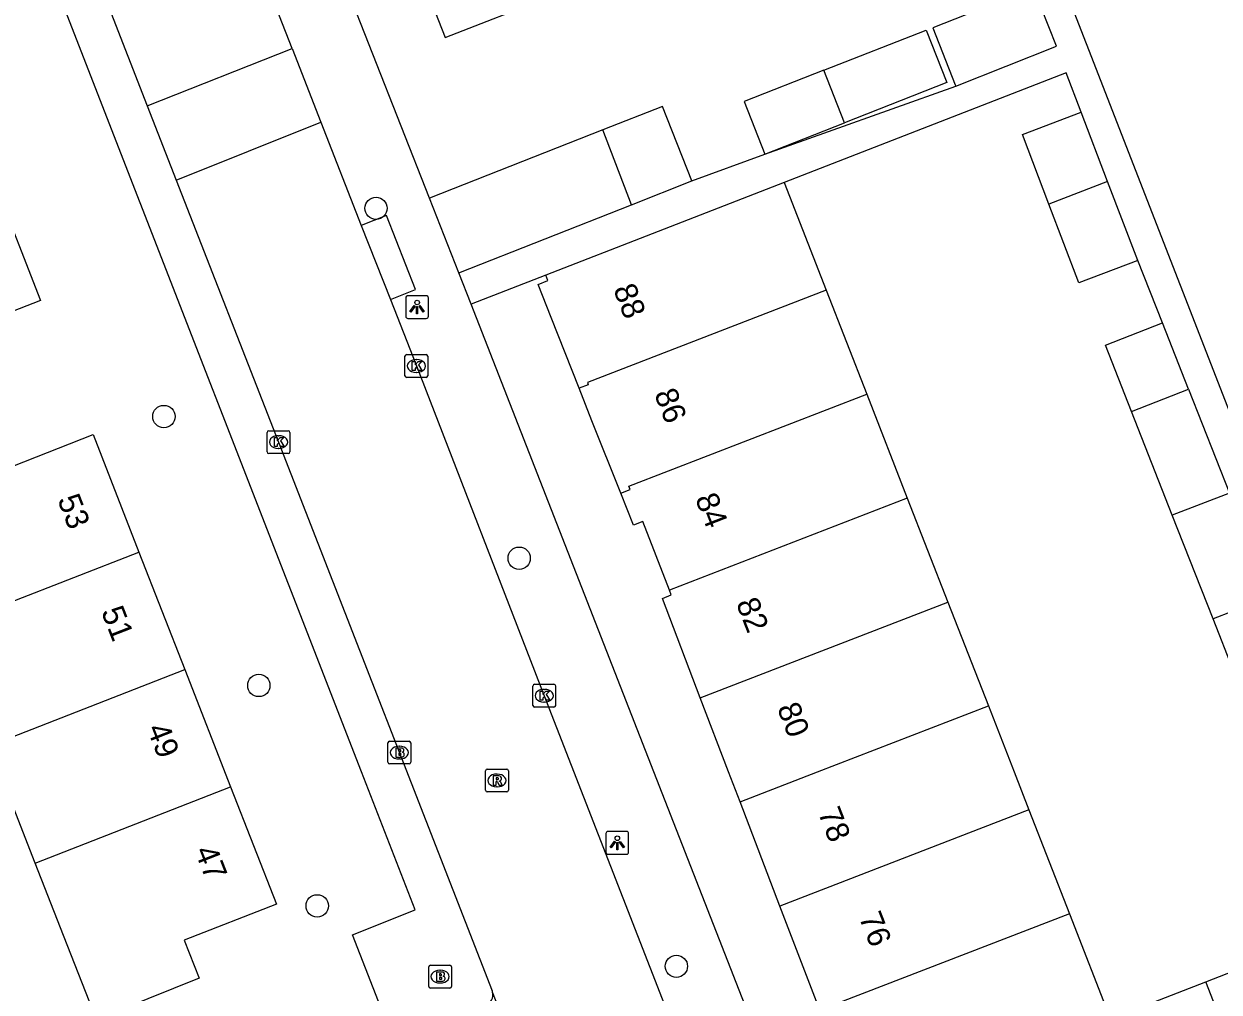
# Model space of a CAD drawing. Extents: x 159689 to 160786, y 387323 to 388339.
# Drawn here: x 159916.1 to 159968.5, y 387740.3 to 387782.8 of the extents above; entities that cross this region are included whole.
import ezdxf

# ---------------------------------------------------------------- set-up
doc = ezdxf.new("R2010")
doc.units = 0
for name, color, linetype in [('IMGEO_Boom', 7, 'Continuous'), ('IMGEO_Brandkraan', 7, 'Continuous'), ('IMGEO_Kolk', 7, 'Continuous'), ('IMGEO_Lichtpunt', 7, 'Continuous'), ('IMGEO_Pand', 7, 'Continuous'), ('IMGEO_Pand_nummerreeks', 7, 'Continuous'), ('IMGEO_Rijbaan_lokaal_open', 7, 'Continuous'), ('IMGEO_Rioolput', 7, 'Continuous'), ('IMGEO_Voetpad_open', 7, 'Continuous')]:
    doc.layers.add(name, color=color, linetype=linetype)

msp = doc.modelspace()

# ---------------------------------------------------------------- linework, layer by layer
at = {"layer": 'IMGEO_Boom'}
for centre in [(159931.561, 387774.715), (159922.264, 387765.584), (159937.836, 387759.371), (159926.425, 387753.791), (159928.983, 387744.127), (159944.727, 387741.478)]:
    msp.add_circle(centre, 0.489, dxfattribs=at)
at = {"layer": 'IMGEO_Brandkraan'}
for p, q in [((159932.082, 387750.423), (159932.082, 387751.275)), ((159932.157, 387751.349), (159933.009, 387751.349)), ((159932.57, 387751.129), (159932.595, 387751.129)), ((159933.083, 387751.275), (159933.083, 387750.423)), ((159932.593, 387750.569), (159932.568, 387750.569)), ((159933.009, 387750.349), (159932.157, 387750.349)), ((159933.945, 387741.525), (159934.797, 387741.525)), ((159933.87, 387740.599), (159933.87, 387741.451)), ((159934.358, 387741.305), (159934.383, 387741.305)), ((159934.871, 387741.451), (159934.871, 387740.599)), ((159934.797, 387740.525), (159933.945, 387740.525)), ((159934.381, 387740.745), (159934.356, 387740.745))]:
    msp.add_line(p, q, dxfattribs=at)
for points in [[(159932.082, 387750.423), (159932.082, 387751.275)], [(159932.157, 387751.349), (159933.009, 387751.349)], [(159932.43, 387751.049), (159932.43, 387750.649), (159932.643, 387750.649)], [(159932.661, 387751.049), (159932.43, 387751.049)], [(159932.609, 387750.968), (159932.555, 387750.968), (159932.555, 387750.892)], [(159933.083, 387751.275), (159933.083, 387750.423)], [(159932.555, 387750.892), (159932.608, 387750.892)], [(159932.617, 387750.816), (159932.555, 387750.816), (159932.555, 387750.735)], [(159932.555, 387750.735), (159932.617, 387750.735)], [(159933.009, 387750.349), (159932.157, 387750.349)], [(159933.945, 387741.525), (159934.797, 387741.525)], [(159933.87, 387740.599), (159933.87, 387741.451)], [(159934.218, 387741.225), (159934.218, 387740.825), (159934.431, 387740.825)], [(159934.449, 387741.225), (159934.218, 387741.225)], [(159934.397, 387741.144), (159934.343, 387741.144), (159934.343, 387741.068)], [(159934.343, 387741.068), (159934.396, 387741.068)], [(159934.405, 387740.992), (159934.343, 387740.992), (159934.343, 387740.911)], [(159934.871, 387741.451), (159934.871, 387740.599)], [(159934.797, 387740.525), (159933.945, 387740.525)], [(159934.343, 387740.911), (159934.405, 387740.911)]]:
    msp.add_lwpolyline(points, dxfattribs=at)
for centre, radius, start, end in [((159932.159, 387751.273), 0.0765, 91.552, 178.448), ((159932.159, 387751.273), 0.0765, 91.552, 178.448), ((159932.61, 387750.93), 0.0379, 267.8285, 90.9355), ((159932.665, 387750.904), 0.145, 59.4692, 91.5367), ((159932.69, 387750.951), 0.0922, 285.5137, 58.1501), ((159933.007, 387751.273), 0.0765, 1.552, 88.448), ((159933.007, 387751.273), 0.0765, 1.552, 88.448), ((159932.159, 387750.425), 0.0765, 181.552, 268.448), ((159932.159, 387750.425), 0.0765, 181.552, 268.448), ((159932.618, 387750.775), 0.0404, 269.8759, 90.5077), ((159932.649, 387750.9), 0.251, 268.6676, 293.5347), ((159932.695, 387750.759), 0.105, 301.3115, 78.989), ((159933.007, 387750.425), 0.0765, 271.552, 358.448), ((159933.007, 387750.425), 0.0765, 271.552, 358.448), ((159933.947, 387741.449), 0.0765, 91.552, 178.448), ((159933.947, 387741.449), 0.0765, 91.552, 178.448), ((159934.795, 387741.449), 0.0765, 1.552, 88.448), ((159934.795, 387741.449), 0.0765, 1.552, 88.448), ((159934.398, 387741.106), 0.0379, 267.8285, 90.9355), ((159934.406, 387740.951), 0.0404, 269.8759, 90.5077), ((159934.453, 387741.08), 0.145, 59.4692, 91.5367), ((159934.478, 387741.127), 0.0922, 285.5137, 58.1501), ((159934.483, 387740.935), 0.105, 301.3115, 78.989), ((159933.947, 387740.601), 0.0765, 181.552, 268.448), ((159933.947, 387740.601), 0.0765, 181.552, 268.448), ((159934.437, 387741.076), 0.251, 268.6676, 293.5347), ((159934.795, 387740.601), 0.0765, 271.552, 358.448), ((159934.795, 387740.601), 0.0765, 271.552, 358.448)]:
    msp.add_arc(centre, radius, start, end, dxfattribs=at)
for centre, major_axis, ratio, start_param, end_param in [((159932.569, 387750.849), (-0.387, 0.002), 0.722429, 4.712389, 7.853982), ((159932.594, 387750.849), (-0.39, 0.002), 0.717154, 1.570796, 4.712389), ((159934.357, 387741.025), (-0.387, 0.002), 0.722429, 4.712389, 7.853982), ((159934.382, 387741.025), (-0.39, 0.002), 0.717154, 1.570796, 4.712389)]:
    msp.add_ellipse(centre, major_axis=major_axis, ratio=ratio, start_param=start_param, end_param=end_param, dxfattribs=at)
at = {"layer": 'IMGEO_Kolk'}
for p, q in [((159932.831, 387767.374), (159932.831, 387768.226)), ((159932.906, 387768.3), (159933.758, 387768.3)), ((159933.832, 387768.226), (159933.832, 387767.374)), ((159933.319, 387768.08), (159933.344, 387768.08)), ((159933.758, 387767.3), (159932.906, 387767.3)), ((159933.342, 387767.52), (159933.317, 387767.52)), ((159926.788, 387764.037), (159926.788, 387764.889)), ((159926.863, 387764.963), (159927.715, 387764.963)), ((159927.276, 387764.743), (159927.301, 387764.743)), ((159927.789, 387764.889), (159927.789, 387764.037)), ((159927.299, 387764.183), (159927.274, 387764.183)), ((159927.715, 387763.963), (159926.863, 387763.963)), ((159938.434, 387752.916), (159938.434, 387753.768)), ((159938.509, 387753.842), (159939.361, 387753.842)), ((159938.922, 387753.622), (159938.947, 387753.622)), ((159939.435, 387753.768), (159939.435, 387752.916)), ((159938.945, 387753.062), (159938.92, 387753.062)), ((159939.361, 387752.842), (159938.509, 387752.842))]:
    msp.add_line(p, q, dxfattribs=at)
for points in [[(159932.831, 387767.374), (159932.831, 387768.226)], [(159932.906, 387768.3), (159933.758, 387768.3)], [(159933.832, 387768.226), (159933.832, 387767.374)], [(159933.152, 387768), (159933.275, 387768), (159933.275, 387767.849), (159933.405, 387768), (159933.569, 387768), (159933.423, 387767.849), (159933.576, 387767.6), (159933.424, 387767.6), (159933.339, 387767.764), (159933.275, 387767.697), (159933.275, 387767.6), (159933.152, 387767.6), (159933.152, 387768)], [(159933.758, 387767.3), (159932.906, 387767.3)], [(159926.788, 387764.037), (159926.788, 387764.889)], [(159926.863, 387764.963), (159927.715, 387764.963)], [(159927.109, 387764.663), (159927.232, 387764.663), (159927.232, 387764.512), (159927.362, 387764.663), (159927.526, 387764.663), (159927.38, 387764.512), (159927.533, 387764.263), (159927.381, 387764.263), (159927.296, 387764.427), (159927.232, 387764.36), (159927.232, 387764.263), (159927.109, 387764.263), (159927.109, 387764.663)], [(159927.789, 387764.889), (159927.789, 387764.037)], [(159927.715, 387763.963), (159926.863, 387763.963)], [(159938.434, 387752.916), (159938.434, 387753.768)], [(159938.509, 387753.842), (159939.361, 387753.842)], [(159938.755, 387753.542), (159938.878, 387753.542), (159938.878, 387753.391), (159939.008, 387753.542), (159939.172, 387753.542), (159939.026, 387753.391), (159939.179, 387753.142), (159939.027, 387753.142), (159938.942, 387753.306), (159938.878, 387753.239), (159938.878, 387753.142), (159938.755, 387753.142), (159938.755, 387753.542)], [(159939.435, 387753.768), (159939.435, 387752.916)], [(159939.361, 387752.842), (159938.509, 387752.842)]]:
    msp.add_lwpolyline(points, dxfattribs=at)
for centre, start, end in [((159932.908, 387768.224), 91.552, 178.448), ((159932.908, 387768.224), 91.552, 178.448), ((159933.756, 387768.224), 1.552, 88.448), ((159933.756, 387768.224), 1.552, 88.448), ((159932.908, 387767.376), 181.552, 268.448), ((159932.908, 387767.376), 181.552, 268.448), ((159933.756, 387767.376), 271.552, 358.448), ((159933.756, 387767.376), 271.552, 358.448), ((159926.865, 387764.887), 91.552, 178.448), ((159926.865, 387764.887), 91.552, 178.448), ((159927.713, 387764.887), 1.552, 88.448), ((159927.713, 387764.887), 1.552, 88.448), ((159926.865, 387764.039), 181.552, 268.448), ((159926.865, 387764.039), 181.552, 268.448), ((159927.713, 387764.039), 271.552, 358.448), ((159927.713, 387764.039), 271.552, 358.448), ((159938.511, 387753.766), 91.552, 178.448), ((159938.511, 387753.766), 91.552, 178.448), ((159939.359, 387753.766), 1.552, 88.448), ((159939.359, 387753.766), 1.552, 88.448), ((159938.511, 387752.918), 181.552, 268.448), ((159938.511, 387752.918), 181.552, 268.448), ((159939.359, 387752.918), 271.552, 358.448), ((159939.359, 387752.918), 271.552, 358.448)]:
    msp.add_arc(centre, 0.0765, start, end, dxfattribs=at)
for centre, major_axis, ratio, start_param, end_param in [((159933.318, 387767.8), (-0.387, 0.002), 0.722429, 4.712389, 7.853982), ((159933.343, 387767.8), (-0.39, 0.002), 0.717154, 1.570796, 4.712389), ((159927.275, 387764.463), (-0.387, 0.002), 0.722429, 4.712389, 7.853982), ((159927.3, 387764.463), (-0.39, 0.002), 0.717154, 1.570796, 4.712389), ((159938.921, 387753.342), (-0.387, 0.002), 0.722429, 4.712389, 7.853982), ((159938.946, 387753.342), (-0.39, 0.002), 0.717154, 1.570796, 4.712389)]:
    msp.add_ellipse(centre, major_axis=major_axis, ratio=ratio, start_param=start_param, end_param=end_param, dxfattribs=at)
at = {"layer": 'IMGEO_Lichtpunt'}
for p, q in [((159933.765, 387770.883), (159932.957, 387770.883)), ((159933.765, 387770.883), (159932.957, 387770.883)), ((159932.863, 387770.788), (159932.863, 387769.981)), ((159932.863, 387770.788), (159932.863, 387769.981)), ((159933.859, 387769.981), (159933.859, 387770.788)), ((159933.859, 387769.981), (159933.859, 387770.788)), ((159932.957, 387769.887), (159933.765, 387769.887)), ((159932.957, 387769.887), (159933.765, 387769.887)), ((159941.638, 387747.294), (159941.638, 387746.487)), ((159941.638, 387747.294), (159941.638, 387746.487)), ((159942.54, 387747.389), (159941.732, 387747.389)), ((159942.54, 387747.389), (159941.732, 387747.389)), ((159942.634, 387746.487), (159942.634, 387747.294)), ((159942.634, 387746.487), (159942.634, 387747.294)), ((159941.732, 387746.393), (159942.54, 387746.393)), ((159941.732, 387746.393), (159942.54, 387746.393))]:
    msp.add_line(p, q, dxfattribs=at)
for points in [[(159933.237, 387770.452), (159933.276, 387770.424), (159933.088, 387770.162), (159933.05, 387770.189), (159933.237, 387770.452)], [(159933.339, 387770.404), (159933.386, 387770.404), (159933.386, 387770.082), (159933.339, 387770.082), (159933.339, 387770.404)], [(159933.449, 387770.424), (159933.487, 387770.451), (159933.674, 387770.189), (159933.635, 387770.161), (159933.449, 387770.424)], [(159942.012, 387746.958), (159942.051, 387746.93), (159941.863, 387746.668), (159941.825, 387746.695), (159942.012, 387746.958)], [(159942.114, 387746.91), (159942.161, 387746.91), (159942.161, 387746.588), (159942.114, 387746.588), (159942.114, 387746.91)], [(159942.224, 387746.93), (159942.262, 387746.957), (159942.449, 387746.695), (159942.41, 387746.667), (159942.224, 387746.93)]]:
    msp.add_lwpolyline(points, dxfattribs=at)
for centre in [(159933.362, 387770.586), (159942.137, 387747.092)]:
    msp.add_circle(centre, 0.0994, dxfattribs=at)
for centre, start, end in [((159932.957, 387770.788), 90, 180), ((159932.957, 387770.788), 90, 180), ((159933.765, 387770.788), 0, 90), ((159933.765, 387770.788), 0, 90), ((159932.957, 387769.981), 180, 270), ((159932.957, 387769.981), 180, 270), ((159933.765, 387769.981), 270, 0), ((159933.765, 387769.981), 270, 360), ((159941.732, 387747.294), 90, 180), ((159941.732, 387747.294), 90, 180), ((159942.54, 387747.294), 0, 90), ((159942.54, 387747.294), 0, 90), ((159941.732, 387746.487), 180, 270), ((159941.732, 387746.487), 180, 270), ((159942.54, 387746.487), 270, 0), ((159942.54, 387746.487), 270, 360)]:
    msp.add_arc(centre, 0.0946, start, end, dxfattribs=at)
at = {"layer": 'IMGEO_Pand'}
for points in [[(159935.682, 387793.345), (159930.956, 387791.493), (159934.596, 387782.206), (159939.252, 387784.031)], [(159960.373, 387784.377), (159955.964, 387782.626), (159956.952, 387780.135), (159956.979, 387780.068)], [(159956.979, 387780.068), (159961.389, 387781.819), (159960.373, 387784.377)], [(159951.195, 387780.774), (159955.672, 387782.532), (159956.578, 387780.227), (159952.1, 387778.466)], [(159951.195, 387780.774), (159947.698, 387779.399), (159948.606, 387777.091)], [(159952.1, 387778.466), (159951.195, 387780.774)], [(159945.403, 387775.915), (159944.117, 387779.178), (159941.506, 387778.149)], [(159961.055, 387774.896), (159959.895, 387777.949), (159962.475, 387778.928)], [(159963.628, 387775.891), (159962.475, 387778.928)], [(159948.606, 387777.091), (159952.1, 387778.466)], [(159941.506, 387778.149), (159933.909, 387775.155)], [(159942.762, 387774.874), (159941.506, 387778.149)], [(159914.846, 387775.821), (159916.857, 387770.671), (159908.283, 387767.326), (159906.28, 387772.477)], [(159949.45, 387775.851), (159943.66, 387773.597), (159939, 387771.782)], [(159942.762, 387774.874), (159945.403, 387775.915)], [(159949.45, 387775.851), (159951.295, 387771.12)], [(159963.628, 387775.891), (159961.055, 387774.896)], [(159964.945, 387772.424), (159963.628, 387775.891)], [(159935.192, 387771.89), (159933.909, 387775.155)], [(159935.192, 387771.89), (159942.762, 387774.874)], [(159964.945, 387772.424), (159962.366, 387771.444), (159961.055, 387774.896)], [(159940.472, 387766.823), (159939.239, 387769.921), (159938.671, 387771.379), (159939.093, 387771.543), (159939, 387771.782)], [(159951.295, 387771.12), (159940.829, 387767.071), (159940.866, 387766.977), (159940.472, 387766.823)], [(159951.295, 387771.12), (159953.072, 387766.563)], [(159964.669, 387765.807), (159963.528, 387768.708), (159966.031, 387769.692)], [(159967.177, 387766.778), (159966.031, 387769.692)], [(159942.295, 387762.226), (159941.026, 387765.399), (159940.472, 387766.823)], [(159964.669, 387765.807), (159967.177, 387766.778)], [(159967.177, 387766.778), (159968.967, 387762.225)], [(159942.295, 387762.226), (159942.695, 387762.381), (159942.638, 387762.527), (159953.072, 387766.563)], [(159953.072, 387766.563), (159954.848, 387762.008)], [(159966.459, 387761.255), (159964.669, 387765.807)], [(159912.597, 387756.297), (159910.59, 387761.427), (159919.157, 387764.792), (159921.167, 387759.643)], [(159944.421, 387757.974), (159943.25, 387760.982), (159942.841, 387760.823), (159942.295, 387762.226)], [(159954.848, 387762.008), (159944.421, 387757.974)], [(159954.848, 387762.008), (159956.625, 387757.451)], [(159968.967, 387762.225), (159966.459, 387761.255)], [(159968.248, 387756.708), (159966.459, 387761.255)], [(159912.597, 387756.297), (159921.167, 387759.643)], [(159921.167, 387759.643), (159923.178, 387754.495)], [(159945.775, 387753.254), (159944.111, 387757.611), (159944.503, 387757.764), (159944.421, 387757.974)], [(159945.775, 387753.254), (159956.625, 387757.451)], [(159956.625, 387757.451), (159958.401, 387752.897)], [(159970.756, 387757.678), (159968.248, 387756.708)], [(159970.038, 387752.156), (159968.248, 387756.708)], [(159914.612, 387751.15), (159923.178, 387754.495)], [(159923.178, 387754.495), (159925.188, 387749.346)], [(159947.52, 387748.686), (159947.018, 387750), (159945.775, 387753.254)], [(159947.52, 387748.686), (159950.915, 387750), (159958.401, 387752.897)], [(159958.401, 387752.897), (159959.531, 387750), (159960.178, 387748.34)], [(159916.626, 387746.003), (159914.612, 387751.15)], [(159925.188, 387749.346), (159927.198, 387744.197), (159923.157, 387742.621), (159923.812, 387740.956), (159919.303, 387739.146), (159917.736, 387743.167), (159916.626, 387746.003)], [(159916.626, 387746.003), (159925.188, 387749.346)], [(159949.265, 387744.117), (159947.52, 387748.686)], [(159960.178, 387748.34), (159949.265, 387744.117)], [(159960.178, 387748.34), (159961.955, 387743.784)], [(159951.009, 387739.55), (159949.265, 387744.117)], [(159961.955, 387743.784), (159951.009, 387739.55)], [(159961.955, 387743.784), (159963.756, 387739.164)], [(159967.926, 387740.79), (159970.663, 387741.857)], [(159965.19, 387739.723), (159967.926, 387740.79)], [(159970.207, 387734.942), (159967.926, 387740.79)]]:
    msp.add_lwpolyline(points, dxfattribs=at)
at = {"layer": 'IMGEO_Rijbaan_lokaal_open'}
for points in [[(159914.429, 387797.56), (159919.835, 387783.57), (159921.528, 387779.204)], [(159927.881, 387781.717), (159926.227, 387785.997), (159923.212, 387793.775)], [(159921.528, 387779.204), (159927.881, 387781.717)], [(159927.881, 387781.717), (159929.141, 387778.491)], [(159921.528, 387779.204), (159922.8, 387775.948)], [(159922.8, 387775.948), (159929.141, 387778.491)], [(159929.141, 387778.491), (159930.916, 387773.964)], [(159922.8, 387775.948), (159927.289, 387764.463), (159936.656, 387740.403)], [(159930.916, 387773.964), (159932.189, 387770.717)], [(159932.189, 387770.717), (159933.332, 387767.8), (159938.935, 387753.342), (159944.752, 387738.393), (159948.776, 387728.153), (159951.643, 387720.816)], [(159940.11, 387731.541), (159936.672, 387740.346)]]:
    msp.add_lwpolyline(points, dxfattribs=at)
msp.add_arc((159936.28, 387740.267), 0.4, 11.4311, 19.928, dxfattribs=at)
at = {"layer": 'IMGEO_Rioolput'}
for p, q in [((159936.362, 387749.199), (159936.362, 387750.051)), ((159936.437, 387750.125), (159937.289, 387750.125)), ((159936.85, 387749.905), (159936.875, 387749.905)), ((159937.363, 387750.051), (159937.363, 387749.199)), ((159936.873, 387749.345), (159936.848, 387749.345)), ((159937.289, 387749.125), (159936.437, 387749.125))]:
    msp.add_line(p, q, dxfattribs=at)
for points in [[(159936.362, 387749.199), (159936.362, 387750.051)], [(159936.437, 387750.125), (159937.289, 387750.125)], [(159937.363, 387750.051), (159937.363, 387749.199)], [(159936.951, 387749.823), (159936.699, 387749.825), (159936.699, 387749.425)], [(159936.699, 387749.425), (159936.823, 387749.425), (159936.823, 387749.587), (159936.834, 387749.587)], [(159936.877, 387749.744), (159936.823, 387749.744), (159936.823, 387749.663)], [(159936.823, 387749.663), (159936.875, 387749.663)], [(159936.881, 387749.558), (159936.952, 387749.425), (159937.092, 387749.425), (159937.027, 387749.551)], [(159937.289, 387749.125), (159936.437, 387749.125)]]:
    msp.add_lwpolyline(points, dxfattribs=at)
for centre, radius, start, end in [((159936.439, 387750.049), 0.0765, 91.552, 178.448), ((159936.439, 387750.049), 0.0765, 91.552, 178.448), ((159937.287, 387750.049), 0.0765, 1.552, 88.448), ((159937.287, 387750.049), 0.0765, 1.552, 88.448), ((159936.833, 387749.534), 0.0533, 26.0293, 88.6989), ((159936.859, 387749.852), 0.19, 274.7715, 282.9687), ((159936.883, 387749.648), 0.0964, 77.0061, 93.1865), ((159936.897, 387749.705), 0.0378, 276.6634, 79.6772), ((159936.95, 387749.713), 0.109, 350.3612, 89.416), ((159936.948, 387749.713), 0.112, 277.5842, 350.9817), ((159936.932, 387749.498), 0.108, 29.5134, 73.7905), ((159936.439, 387749.201), 0.0765, 181.552, 268.448), ((159936.439, 387749.201), 0.0765, 181.552, 268.448), ((159937.287, 387749.201), 0.0765, 271.552, 358.448), ((159937.287, 387749.201), 0.0765, 271.552, 358.448)]:
    msp.add_arc(centre, radius, start, end, dxfattribs=at)
for centre, major_axis, ratio, start_param, end_param in [((159936.849, 387749.625), (-0.387, 0.002), 0.722429, 4.712389, 7.853982), ((159936.874, 387749.625), (-0.39, 0.002), 0.717154, 1.570796, 4.712389)]:
    msp.add_ellipse(centre, major_axis=major_axis, ratio=ratio, start_param=start_param, end_param=end_param, dxfattribs=at)
at = {"layer": 'IMGEO_Voetpad_open'}
for points in [[(159954.35, 387803.411), (159975.149, 387749.886), (159981.77, 387752.459)], [(159988.008, 387595.398), (159930.533, 387742.858), (159933.271, 387743.95), (159930.92, 387750), (159918.022, 387783.189), (159912.569, 387796.796)], [(159933.909, 387775.155), (159927.698, 387790.952)], [(159962.475, 387778.928), (159961.805, 387780.652), (159949.45, 387775.851)], [(159948.606, 387777.091), (159956.979, 387780.068)], [(159945.403, 387775.915), (159948.606, 387777.091)], [(159932.189, 387770.717), (159933.291, 387771.15), (159932.015, 387774.396), (159930.916, 387773.964)], [(159966.031, 387769.692), (159964.945, 387772.424)], [(159935.732, 387770.506), (159935.192, 387771.89)], [(159939, 387771.782), (159935.732, 387770.506)], [(159952.338, 387727.973), (159943.738, 387750), (159935.732, 387770.506)]]:
    msp.add_lwpolyline(points, dxfattribs=at)
msp.add_arc((159936.167, 387740.231), 0.518, 293.7991, 12.8376, dxfattribs=at)

# ---------------------------------------------------------------- texts
at = {"layer": 'IMGEO_Pand_nummerreeks'}
for s, rotation, p in [('88', 291.3654, (159941.945, 387771.171)), ('86', 291.3654, (159943.74, 387766.584)), ('53', 291.3253, (159917.584, 387761.947)), ('84', 291.3629, (159945.534, 387761.994)), ('51', 291.3253, (159919.501, 387757.037)), ('82', 291.3629, (159947.329, 387757.407)), ('80', 291.3629, (159949.126, 387752.811)), ('49', 291.3253, (159921.504, 387751.906)), ('78', 291.3629, (159950.921, 387748.221)), ('47', 291.3253, (159923.598, 387746.542)), ('76', 291.3629, (159952.716, 387743.634))]:
    msp.add_text(s, height=1, rotation=rotation, dxfattribs=at).set_placement(p)

doc.saveas('drawing.dxf')
